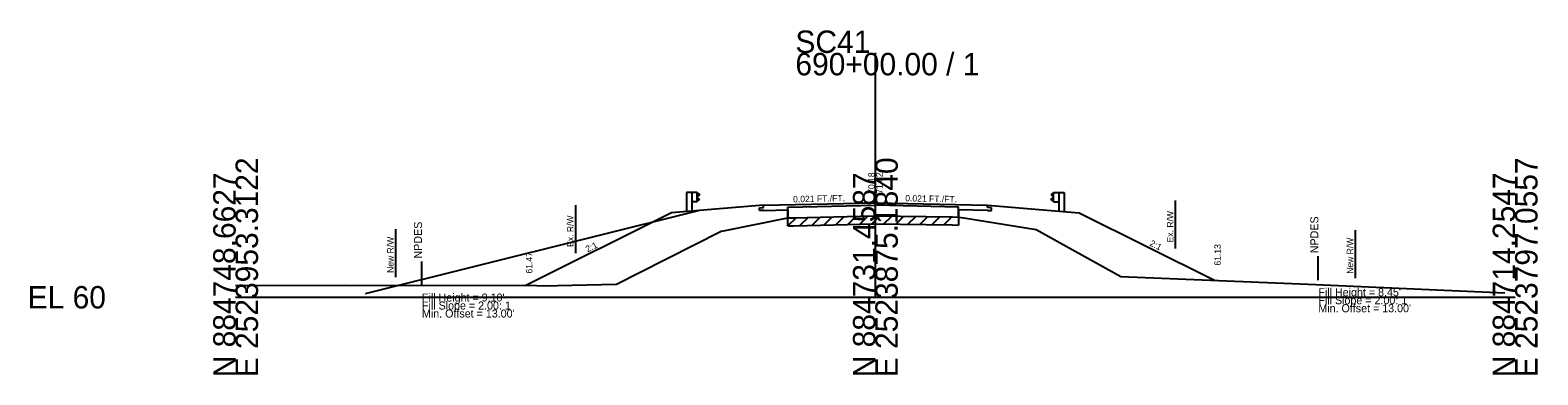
# Model space of a CAD drawing. Extents: x -26 to 183, y -10 to 24021.
# Drawn here: x -25.7 to 162.8, y 16990.3 to 17033.4 of the extents above; entities that cross this region are included whole.
import ezdxf

# ---------------------------------------------------------------- set-up
doc = ezdxf.new("R2010")
doc.units = 0
for name, color, linetype in [('RD_GPK_XS_Cell', 7, 'Continuous'), ('RD_XS_Base', 7, 'Continuous'), ('RD_XS_Buildup', 7, 'Continuous'), ('RD_XS_EarthShd', 7, 'Continuous'), ('RD_XS_ExGround', 7, 'Continuous'), ('RD_XS_ExPaveRet', 7, 'Continuous'), ('RD_XS_ExRW', 7, 'Continuous'), ('RD_XS_GR', 7, 'Continuous'), ('RD_XS_NewRW', 7, 'Continuous'), ('RD_XS_NPDES', 7, 'Continuous'), ('RD_XS_Pave', 7, 'Continuous'), ('RD_XS_TieSlope', 7, 'Continuous'), ('RD_XS_TX_Elev_EX', 7, 'Continuous'), ('RD_XS_TX_Elev_PR', 7, 'Continuous'), ('RD_XS_TX_Slope', 7, 'Continuous'), ('RD_XS_TX_Warning', 7, 'Continuous')]:
    doc.layers.add(name, color=color, linetype=linetype)

msp = doc.modelspace()

# ---------------------------------------------------------------- linework, layer by layer
at = {"layer": 'RD_GPK_XS_Cell'}
for p, q in [((80, 17000), (80, 17030.54)), ((0, 17000), (80, 17000)), ((80, 17000), (160, 17000))]:
    msp.add_line(p, q, dxfattribs=at)
at = {"layer": 'RD_XS_Base'}
for p, q in [((66, 17010.85), (69.05, 17010.91)), ((69.05, 17010.91), (69.05, 17009.92)), ((90.38, 17010.92), (90.38, 17010.02)), ((94, 17010.85), (90.38, 17010.92))]:
    msp.add_line(p, q, dxfattribs=at)
at = {"layer": 'RD_XS_Buildup'}
for p, q in [((69.05, 17011.27), (80, 17011.5)), ((90.38, 17011.28), (80, 17011.5)), ((69.05, 17009.92), (69.05, 17011.27)), ((90.38, 17010.02), (90.38, 17011.28))]:
    msp.add_line(p, q, dxfattribs=at)
at = {"layer": 'RD_XS_EarthShd'}
for p, q in [((66, 17011.53), (58, 17010.86)), ((94, 17011.53), (102, 17010.86)), ((58, 17010.86), (54.5, 17010.57)), ((102, 17010.86), (105.5, 17010.57))]:
    msp.add_line(p, q, dxfattribs=at)
at = {"layer": 'RD_XS_ExGround'}
for p, q in [((61.21, 17008.35), (69.05, 17009.92)), ((69.05, 17009.92), (69.8, 17009.94)), ((69.8, 17009.94), (79.81, 17010.18)), ((79.81, 17010.18), (89.64, 17010.04)), ((89.64, 17010.04), (90.38, 17010.02)), ((90.38, 17010.02), (91.07, 17009.91)), ((91.07, 17009.91), (100.11, 17008.47)), ((50.57, 17003.13), (60.73, 17008.25)), ((60.73, 17008.25), (61.21, 17008.35)), ((100.11, 17008.47), (110.71, 17002.6)), ((47.61, 17001.64), (50.57, 17003.13)), ((110.71, 17002.6), (134.13, 17001.64)), ((0, 17001.47), (13.65, 17001.51)), ((13.65, 17001.51), (37.61, 17001.47)), ((37.61, 17001.47), (39.22, 17001.45)), ((39.22, 17001.45), (40.26, 17001.46)), ((40.26, 17001.46), (47.61, 17001.64)), ((134.13, 17001.64), (158.73, 17000.55))]:
    msp.add_line(p, q, dxfattribs=at)
at = {"layer": 'RD_XS_ExPaveRet'}
for p, q in [((69.05, 17008.92), (70.08, 17009.95)), ((69.05, 17008.92), (69.05, 17009.92)), ((70.55, 17008.96), (71.58, 17009.98)), ((72.05, 17008.99), (73.08, 17010.02)), ((73.55, 17009.03), (74.58, 17010.05)), ((75.05, 17009.07), (76.08, 17010.09)), ((76.55, 17009.1), (77.58, 17010.13)), ((78.05, 17009.14), (79.08, 17010.16)), ((79.55, 17009.17), (80.55, 17010.17)), ((81.05, 17009.16), (82.04, 17010.15)), ((82.55, 17009.14), (83.54, 17010.13)), ((84.05, 17009.12), (85.04, 17010.1)), ((85.55, 17009.1), (86.54, 17010.08)), ((87.05, 17009.07), (88.04, 17010.06)), ((88.55, 17009.05), (89.54, 17010.04)), ((90.38, 17010.02), (90.38, 17009.02)), ((69.05, 17008.92), (69.8, 17008.94)), ((69.8, 17008.94), (79.81, 17009.18)), ((79.81, 17009.18), (89.64, 17009.04)), ((89.64, 17009.04), (90.38, 17009.02))]:
    msp.add_line(p, q, dxfattribs=at)
at = {"layer": 'RD_XS_ExRW'}
for p, q in [((42.5, 17011.52), (42.5, 17005.52)), ((117.5, 17012.08), (117.5, 17006.08))]:
    msp.add_line(p, q, dxfattribs=at)
at = {"layer": 'RD_XS_GR'}
for p, q in [((56.4, 17013.11), (56.4, 17010.73)), ((57.06, 17013.11), (56.4, 17013.11)), ((57.06, 17013.11), (57.06, 17010.78)), ((57.73, 17013.11), (57.06, 17013.11)), ((57.73, 17011.95), (57.06, 17011.95)), ((57.73, 17011.95), (57.73, 17013.11)), ((57.73, 17013.04), (58, 17012.84)), ((58, 17012.79), (57.73, 17012.59)), ((58, 17012.27), (57.73, 17012.47)), ((57.73, 17012.02), (58, 17012.22)), ((58, 17012.84), (58, 17012.79)), ((58, 17012.22), (58, 17012.27)), ((102.27, 17013.04), (102, 17012.84)), ((102, 17012.84), (102, 17012.79)), ((102, 17012.79), (102.27, 17012.59)), ((102, 17012.27), (102.27, 17012.47)), ((102, 17012.22), (102, 17012.27)), ((102.27, 17012.02), (102, 17012.22)), ((102.27, 17013.11), (102.94, 17013.11)), ((102.27, 17011.95), (102.27, 17013.11)), ((102.27, 17011.95), (102.94, 17011.95)), ((102.94, 17013.11), (102.94, 17010.78)), ((102.94, 17013.11), (103.6, 17013.11)), ((103.6, 17013.11), (103.6, 17010.73))]:
    msp.add_line(p, q, dxfattribs=at)
at = {"layer": 'RD_XS_NewRW'}
for p, q in [((20, 17008.5), (20, 17002.5)), ((140, 17008.38), (140, 17002.38))]:
    msp.add_line(p, q, dxfattribs=at)
at = {"layer": 'RD_XS_NPDES'}
for p, q in [((23.3, 17001.47), (23.3, 17004.47)), ((135.39, 17002.13), (135.39, 17005.13))]:
    msp.add_line(p, q, dxfattribs=at)
at = {"layer": 'RD_XS_Pave'}
for p, q in [((66, 17011.53), (80, 17011.82)), ((66, 17011.21), (66, 17011.53)), ((80, 17011.82), (94, 17011.53)), ((94, 17011.21), (94, 17011.53)), ((58, 17010.86), (16.21, 17000.41)), ((65.5, 17011.2), (66, 17011.21)), ((65.5, 17010.84), (65.5, 17011.2)), ((66, 17010.85), (65.5, 17010.84)), ((94.5, 17011.2), (94, 17011.21)), ((94, 17010.85), (94.5, 17010.84)), ((94.5, 17010.84), (94.5, 17011.2))]:
    msp.add_line(p, q, dxfattribs=at)
at = {"layer": 'RD_XS_TieSlope'}
for p, q in [((54.5, 17010.57), (36.3, 17001.47)), ((105.5, 17010.57), (122.39, 17002.13))]:
    msp.add_line(p, q, dxfattribs=at)

# ---------------------------------------------------------------- texts
at = {"layer": 'RD_GPK_XS_Cell'}
for s, p in [('SC41', (70, 17030.54)), ('690+00.00 / 1', (70, 17027.74)), ('EL 60', (-26, 16998.6))]:
    msp.add_text(s, height=2.8, dxfattribs=at).set_placement(p)
for s, p in [('E 2523953.3122', (2.8, 16990)), ('E 2523875.1840', (82.8, 16990)), ('E 2523797.0557', (162.8, 16990)), ('N 884748.6627', (0, 16990)), ('N 884731.4587', (80, 16990)), ('N 884714.2547', (160, 16990))]:
    msp.add_text(s, height=2.8, rotation=90, dxfattribs=at).set_placement(p)
at = {"layer": 'RD_XS_ExRW'}
for p in [(42.25, 17006.3), (117.25, 17006.86)]:
    msp.add_text('Ex. R/W ', height=0.8, rotation=90, dxfattribs=at).set_placement(p)
at = {"layer": 'RD_XS_NewRW'}
for p in [(19.75, 17003.05), (139.75, 17002.93)]:
    msp.add_text('New R/W ', height=0.8, rotation=90, dxfattribs=at).set_placement(p)
at = {"layer": 'RD_XS_TX_Elev_EX'}
msp.add_text('70.18', height=0.8, rotation=90, dxfattribs=at).set_placement((79.9, 17012.93))
at = {"layer": 'RD_XS_TX_Elev_PR'}
for s, p in [('71.82', (80.9, 17012.93)), ('61.13', (123.19, 17003.96)), ('61.47', (37.1, 17002.97))]:
    msp.add_text(s, height=0.8, rotation=90, dxfattribs=at).set_placement(p)
at = {"layer": 'RD_XS_TX_Slope'}
for s, rotation, p in [('0.021 FT./FT.', 1.1916, (69.72, 17011.86)), ('0.021 FT./FT.', 358.8084, (83.73, 17011.99)), ('2:1', 26.5651, (44.01, 17005.6)), ('2:1', 333.4349, (114.22, 17006.49))]:
    msp.add_text(s, height=0.8, rotation=rotation, dxfattribs=at).set_placement(p)
at = {"layer": 'RD_XS_TX_Warning'}
for p in [(135.39, 17005.13), (23.3, 17004.47)]:
    msp.add_text(' NPDES', height=1, rotation=90, dxfattribs=at).set_placement(p)
for s, p in [("Fill Height = 9.10' ", (23.3, 16999.47)), ("Fill Height = 8.45' ", (135.39, 17000.13)), ('Fill Slope = 2.00: 1', (135.39, 16999.13)), ('Fill Slope = 2.00: 1', (23.3, 16998.47)), ("Min. Offset = 13.00' ", (23.3, 16997.47)), ("Min. Offset = 13.00' ", (135.39, 16998.13))]:
    msp.add_text(s, height=1, dxfattribs=at).set_placement(p)

doc.saveas('drawing.dxf')
